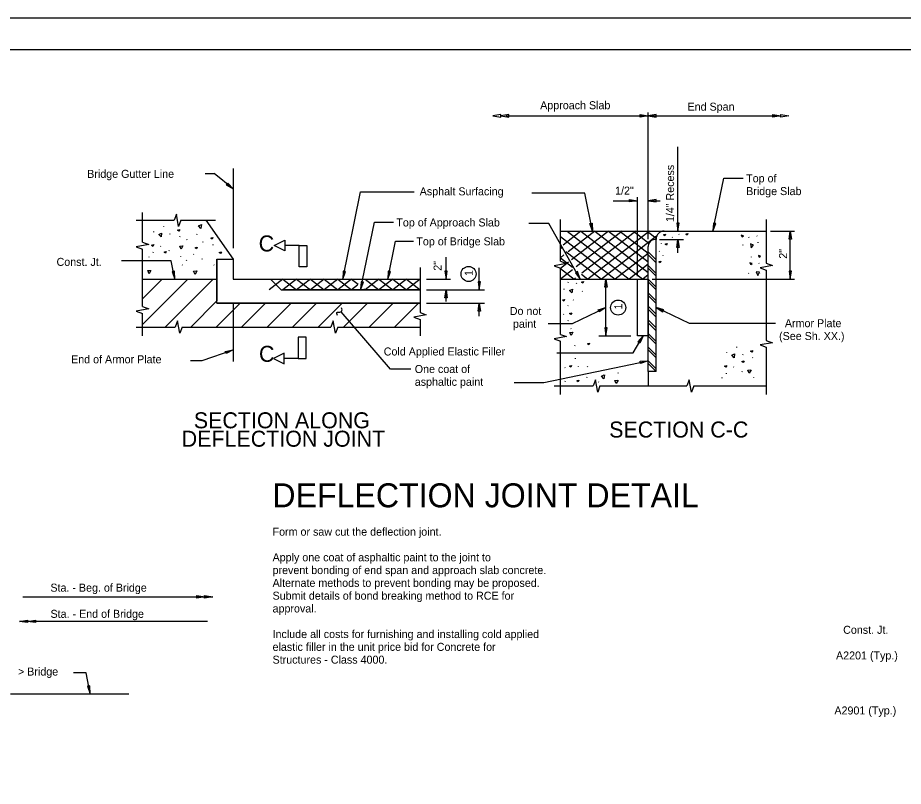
# Model space of a CAD drawing. Extents: x -129.8 to -33.5, y -497.5 to -438.8.
# Drawn here: x -89.34 to -52.46, y -470.81 to -438.78 of the extents above; entities that cross this region are included whole.
import ezdxf

# ---------------------------------------------------------------- set-up
doc = ezdxf.new("R2010")
doc.units = 0
for name, color, linetype in [('BR_AUTO DIMENSION', 7, 'Continuous'), ('BR_BORDER LINES', 7, 'Continuous'), ('BR_CENTER LINES', 7, 'Continuous'), ('BR_CONCRETE', 7, 'Continuous'), ('BR_STRUCTURAL STEEL', 7, 'Continuous'), ('BR_TABLE LINES', 7, 'Continuous'), ('BR_TEXT', 7, 'Continuous'), ('Default', 7, 'Continuous'), ('RD_SHT_IplotShp', 7, 'Continuous')]:
    doc.layers.add(name, color=color, linetype=linetype)

# ---------------------------------------------------------------- blocks, each defined once
blk = doc.blocks.new('CONCRT')
at = {"layer": 'Default'}
for p, q in [((-1.318, 1.18), (-1.295, 1.146)), ((0.991, 0.781), (1.013, 0.831)), ((1.319, 1.192), (1.341, 1.159)), ((-0.324, 0.653), (-0.302, 0.703)), ((0.37, 0.298), (0.392, 0.265)), ((-1.223, -0.529), (-1.201, -0.479)), ((-0.38, -0.757), (-0.357, -0.707)), ((0.125, -1.4), (0.148, -1.35)), ((0.94, -0.896), (0.946, -0.946))]:
    blk.add_line(p, q, dxfattribs=at)
for points in [[(-1.073, 0.503), (-0.924, 0.786), (-0.807, 0.526), (-1.068, 0.503)], [(0.952, 0.154), (1.019, 0.292), (1.13, 0.209), (0.952, 0.154)], [(-0.49, -0.243), (-0.423, -0.104), (-0.312, -0.188), (-0.49, -0.243)], [(0.296, -0.814), (0.34, -0.497), (0.538, -0.702), (0.301, -0.812)], [(-1.212, -1.112), (-1.146, -0.973), (-1.035, -1.056), (-1.212, -1.112)]]:
    blk.add_lwpolyline(points, dxfattribs=at)

msp = doc.modelspace()

# ---------------------------------------------------------------- linework, layer by layer
at = {"layer": 'BR_AUTO DIMENSION'}
for p, q in [((-69.004, -442.871), (-57.581, -442.871)), ((-63.084, -448.01), (-63.084, -442.729)), ((-61.841, -447.675), (-61.841, -444.157)), ((-80.362, -445.067), (-80.362, -448.386)), ((-81.535, -445.277), (-81.161, -445.277)), ((-80.362, -445.919), (-81.161, -445.277)), ((-60.382, -447.675), (-59.935, -445.476)), ((-59.935, -445.476), (-59.122, -445.476)), ((-75.801, -449.675), (-75.061, -446.035)), ((-75.061, -446.035), (-72.82, -446.035)), ((-65.715, -446.091), (-67.929, -446.091)), ((-65.394, -447.675), (-65.715, -446.091)), ((-64.544, -446.408), (-63.528, -446.408)), ((-63.528, -449.552), (-63.528, -446.265)), ((-63.084, -446.408), (-62.58, -446.408)), ((-84.397, -447.22), (-82.827, -447.22)), ((-82.538, -447.22), (-81.095, -447.22)), ((-75.056, -450.119), (-74.484, -447.304)), ((-74.484, -447.304), (-73.682, -447.304)), ((-67.211, -447.356), (-68.047, -447.356)), ((-65.907, -449.675), (-67.211, -447.356)), ((-58.164, -447.187), (-58.164, -449.014)), ((-57.99, -447.675), (-56.985, -447.675)), ((-57.163, -449.675), (-57.163, -447.675)), ((-73.923, -449.675), (-73.602, -448.091)), ((-73.602, -448.091), (-72.858, -448.091)), ((-62.607, -448.029), (-61.607, -448.029)), ((-61.841, -448.575), (-61.841, -448.029)), ((-71.5, -449.675), (-71.5, -448.764)), ((-82.941, -448.911), (-85.008, -448.911)), ((-82.798, -449.675), (-82.941, -448.911)), ((-72.578, -449.197), (-72.578, -451.072)), ((-70.113, -450.119), (-70.113, -449.209)), ((-58.164, -449.304), (-58.164, -452.229)), ((-72.306, -449.675), (-71.313, -449.675)), ((-64.84, -452.045), (-64.84, -449.675)), ((-62.914, -449.675), (-56.985, -449.675)), ((-72.306, -450.119), (-69.898, -450.119)), ((-71.5, -450.605), (-71.5, -450.119)), ((-72.306, -450.675), (-69.898, -450.675)), ((-70.113, -451.22), (-70.113, -450.675)), ((-73.813, -453.428), (-75.872, -451.04)), ((-66.229, -451.529), (-64.84, -450.86)), ((-61.361, -451.529), (-62.75, -450.86)), ((-72.578, -451.361), (-72.578, -452.045)), ((-84.397, -451.675), (-82.781, -451.675)), ((-82.492, -451.675), (-76.296, -451.675)), ((-76.007, -451.675), (-72.578, -451.675)), ((-67.241, -451.529), (-66.229, -451.529)), ((-57.78, -451.529), (-61.361, -451.529)), ((-65.132, -452.045), (-63.802, -452.045)), ((-63.711, -452.742), (-63.289, -452.042)), ((-58.164, -452.518), (-58.164, -454.491)), ((-81.653, -453.074), (-80.362, -452.623)), ((-66.888, -452.742), (-63.711, -452.742)), ((-82.141, -453.074), (-81.653, -453.074)), ((-67.428, -453.991), (-63.084, -453.076)), ((-72.962, -453.428), (-73.813, -453.428)), ((-68.662, -453.991), (-67.428, -453.991)), ((-66.993, -454.124), (-65.377, -454.124)), ((-65.088, -454.124), (-61.47, -454.124)), ((-61.181, -454.124), (-58.164, -454.124)), ((-89.124, -462.917), (-81.217, -462.917)), ((-81.436, -463.941), (-89.258, -463.941)), ((-86.483, -466.077), (-87.016, -466.077)), ((-86.317, -466.964), (-86.483, -466.077))]:
    msp.add_line(p, q, dxfattribs=at)
for points in [[(-69.218, -442.821), (-69.551, -442.871), (-69.218, -442.921)], [(-68.885, -442.821), (-69.218, -442.871), (-68.885, -442.921)], [(-63.417, -442.821), (-63.084, -442.871), (-63.417, -442.921)], [(-62.751, -442.821), (-63.084, -442.871), (-62.751, -442.921)], [(-57.883, -442.821), (-57.55, -442.871), (-57.883, -442.921)], [(-57.55, -442.821), (-57.217, -442.871), (-57.55, -442.921)], [(-80.653, -445.749), (-80.362, -445.919), (-80.59, -445.671)], [(-63.862, -446.358), (-63.528, -446.408), (-63.862, -446.458)], [(-62.751, -446.358), (-63.084, -446.408), (-62.751, -446.458)], [(-65.411, -447.338), (-65.394, -447.675), (-65.509, -447.358)], [(-61.891, -447.341), (-61.841, -447.675), (-61.791, -447.341)], [(-60.364, -447.338), (-60.382, -447.675), (-60.266, -447.358)], [(-57.213, -448.008), (-57.163, -447.675), (-57.113, -448.008)], [(-61.891, -448.363), (-61.841, -448.029), (-61.791, -448.363)], [(-82.909, -449.356), (-82.798, -449.675), (-82.81, -449.338)], [(-75.783, -449.338), (-75.801, -449.675), (-75.685, -449.358)], [(-73.906, -449.338), (-73.923, -449.675), (-73.808, -449.358)], [(-71.55, -449.341), (-71.5, -449.675), (-71.45, -449.341)], [(-66.114, -449.409), (-65.907, -449.675), (-66.027, -449.36)], [(-57.213, -449.341), (-57.163, -449.675), (-57.113, -449.341)], [(-75.039, -449.783), (-75.056, -450.119), (-74.941, -449.802)], [(-70.163, -449.786), (-70.113, -450.119), (-70.063, -449.786)], [(-64.89, -450.008), (-64.84, -449.675), (-64.79, -450.008)], [(-71.55, -450.452), (-71.5, -450.119), (-71.45, -450.452)], [(-70.163, -451.008), (-70.113, -450.675), (-70.063, -451.008)], [(-65.165, -450.951), (-64.84, -450.86), (-65.124, -451.042)], [(-62.425, -450.951), (-62.75, -450.86), (-62.466, -451.042)], [(-64.89, -451.712), (-64.84, -452.045), (-64.79, -451.712)], [(-63.511, -452.296), (-63.289, -452.042), (-63.427, -452.35)], [(-80.693, -452.686), (-80.362, -452.623), (-80.66, -452.78)], [(-63.42, -453.099), (-63.084, -453.076), (-63.399, -453.197)], [(-81.884, -462.867), (-81.55, -462.917), (-81.884, -462.967)], [(-81.551, -462.867), (-81.217, -462.917), (-81.551, -462.967)], [(-88.925, -463.991), (-89.258, -463.941), (-88.925, -463.891)], [(-88.592, -463.991), (-88.925, -463.941), (-88.592, -463.891)], [(-86.427, -466.645), (-86.317, -466.964), (-86.329, -466.627)]]:
    msp.add_lwpolyline(points, close=True, dxfattribs=at)
for points in [[(-84.14, -448.14), (-84.14, -446.897)], [(-82.538, -447.22), (-82.634, -447.477), (-82.73, -446.963), (-82.827, -447.22)], [(-66.736, -448.929), (-66.736, -447.187)], [(-84.14, -448.14), (-83.882, -448.236), (-84.397, -448.333), (-84.14, -448.429)], [(-84.14, -450.819), (-84.14, -448.429)], [(-66.736, -448.929), (-66.478, -449.025), (-66.993, -449.122), (-66.736, -449.218)], [(-58.164, -449.014), (-57.906, -449.111), (-58.421, -449.207), (-58.164, -449.304)], [(-66.736, -451.978), (-66.736, -449.218)], [(-84.14, -450.819), (-83.882, -450.915), (-84.397, -451.012), (-84.14, -451.108)], [(-84.14, -452.045), (-84.14, -451.108)], [(-72.578, -451.072), (-72.32, -451.168), (-72.835, -451.265), (-72.578, -451.361)], [(-82.492, -451.675), (-82.588, -451.932), (-82.685, -451.417), (-82.781, -451.675)], [(-76.007, -451.675), (-76.103, -451.932), (-76.2, -451.417), (-76.296, -451.675)], [(-66.736, -451.978), (-66.478, -452.074), (-66.993, -452.171), (-66.736, -452.267)], [(-66.736, -454.491), (-66.736, -452.267)], [(-58.164, -452.229), (-57.906, -452.325), (-58.421, -452.421), (-58.164, -452.518)], [(-65.088, -454.124), (-65.184, -454.382), (-65.281, -453.867), (-65.377, -454.124)], [(-61.181, -454.124), (-61.277, -454.382), (-61.374, -453.867), (-61.47, -454.124)]]:
    msp.add_lwpolyline(points, dxfattribs=at)
at = {"layer": 'BR_BORDER LINES'}
for p, q in [((-129.766, -438.782), (-33.766, -438.782)), ((-35.099, -440.119), (-124.877, -440.119))]:
    msp.add_line(p, q, dxfattribs=at)
at = {"layer": 'BR_CENTER LINES'}
for p, q in [((-82.253, -449.675), (-84.14, -451.561)), ((-83.314, -449.675), (-84.14, -450.5)), ((-81.193, -449.675), (-83.193, -451.675)), ((-81.038, -450.581), (-82.132, -451.675)), ((-80.071, -450.675), (-81.071, -451.675)), ((-79.011, -450.675), (-80.011, -451.675)), ((-77.95, -450.675), (-78.95, -451.675)), ((-76.889, -450.675), (-77.889, -451.675)), ((-75.829, -450.675), (-76.829, -451.675)), ((-74.768, -450.675), (-75.768, -451.675)), ((-73.707, -450.675), (-74.707, -451.675)), ((-72.647, -450.675), (-73.647, -451.675)), ((-89.634, -466.964), (-84.715, -466.964))]:
    msp.add_line(p, q, dxfattribs=at)
at = {"layer": 'BR_CONCRETE'}
for p, q in [((-62.417, -447.675), (-58.164, -447.675)), ((-62.751, -448.008), (-62.751, -448.029)), ((-81.038, -448.851), (-80.362, -448.851)), ((-84.14, -449.675), (-81.038, -449.675)), ((-80.362, -449.675), (-72.578, -449.675)), ((-66.736, -449.675), (-63.528, -449.675)), ((-81.038, -450.675), (-72.578, -450.675)), ((-63.084, -453.527), (-63.084, -454.124))]:
    msp.add_line(p, q, dxfattribs=at)
msp.add_lwpolyline([(-81.503, -447.22), (-80.362, -448.851), (-80.362, -449.675)], dxfattribs=at)
msp.add_arc((-62.417, -448.008), 0.333, 90, 180, dxfattribs=at)
at = {"layer": 'BR_STRUCTURAL STEEL'}
for p, q in [((-62.751, -448.029), (-62.8, -448.029)), ((-62.751, -453.527), (-62.751, -448.029)), ((-63.084, -453.527), (-63.084, -448.314)), ((-63.084, -448.541), (-62.751, -448.874)), ((-63.084, -448.659), (-62.751, -448.992)), ((-63.084, -449.108), (-62.751, -449.441)), ((-63.084, -449.226), (-62.751, -449.559)), ((-63.084, -449.675), (-62.751, -450.008)), ((-63.084, -449.793), (-62.751, -450.126)), ((-63.084, -450.242), (-62.751, -450.575)), ((-63.084, -450.359), (-62.751, -450.693)), ((-63.084, -450.808), (-62.751, -451.142)), ((-63.084, -450.926), (-62.751, -451.26)), ((-63.084, -451.375), (-62.751, -451.709)), ((-63.084, -451.493), (-62.751, -451.826)), ((-63.084, -451.942), (-62.751, -452.275)), ((-63.084, -452.06), (-62.751, -452.393)), ((-63.084, -452.509), (-62.751, -452.842)), ((-63.084, -452.627), (-62.751, -452.96)), ((-63.084, -453.076), (-62.751, -453.409)), ((-63.084, -453.194), (-62.751, -453.527)), ((-62.751, -453.527), (-63.084, -453.527))]:
    msp.add_line(p, q, dxfattribs=at)
msp.add_arc((-62.8, -448.314), 0.284, 90, 180, dxfattribs=at)
at = {"layer": 'BR_TABLE LINES'}
for p, q in [((-83.666, -447.715), (-83.669, -447.69)), ((-83.259, -447.463), (-83.27, -447.488)), ((-66.736, -447.675), (-62.417, -447.675)), ((-65.879, -447.675), (-66.626, -448.256)), ((-66.45, -447.675), (-63.879, -449.675)), ((-65.307, -447.675), (-66.417, -448.538)), ((-64.736, -447.675), (-66.267, -448.866)), ((-64.164, -447.675), (-66.074, -449.16)), ((-65.879, -447.675), (-63.307, -449.675)), ((-63.593, -447.675), (-65.841, -449.423)), ((-63.021, -447.675), (-65.593, -449.675)), ((-65.307, -447.675), (-63.084, -449.404)), ((-64.736, -447.675), (-63.084, -448.959)), ((-64.265, -447.675), (-63.084, -448.594)), ((-63.694, -447.675), (-63.049, -448.177)), ((-63.123, -447.675), (-62.748, -447.966)), ((-83.006, -447.785), (-83.017, -447.81)), ((-82.585, -447.899), (-82.596, -447.924)), ((-82.286, -448.055), (-82.289, -448.03)), ((-81.879, -447.802), (-81.89, -447.827)), ((-66.736, -447.897), (-64.45, -449.675)), ((-62.73, -447.893), (-65.021, -449.675)), ((-62.074, -447.939), (-62.085, -447.922)), ((-61.793, -447.817), (-61.804, -447.801)), ((-58.904, -447.915), (-58.893, -447.94)), ((-58.556, -447.867), (-58.545, -447.892)), ((-83.381, -448.312), (-83.392, -448.296)), ((-81.626, -448.124), (-81.638, -448.149)), ((-81.205, -448.238), (-81.216, -448.263)), ((-77.619, -448.276), (-78.211, -448.276)), ((-66.736, -448.341), (-66.676, -448.388)), ((-62.52, -448.192), (-62.531, -448.176)), ((-59.156, -448.237), (-59.145, -448.262)), ((-58.496, -448.167), (-58.494, -448.142)), ((-83.856, -448.759), (-83.867, -448.743)), ((-83.692, -448.554), (-83.703, -448.579)), ((-83.034, -448.49), (-83.045, -448.515)), ((-82.537, -448.753), (-82.548, -448.736)), ((-82.001, -448.651), (-82.012, -448.635)), ((-81.654, -448.829), (-81.665, -448.854)), ((-66.587, -448.67), (-66.736, -448.786)), ((-66.736, -448.786), (-66.238, -449.173)), ((-66.508, -448.519), (-65.021, -449.675)), ((-63.084, -448.612), (-64.45, -449.675)), ((-62.613, -448.527), (-62.624, -448.51)), ((-62.45, -448.706), (-62.461, -448.689)), ((-58.782, -448.764), (-58.771, -448.747)), ((-82.476, -449.099), (-82.487, -449.082)), ((-82.312, -448.893), (-82.323, -448.918)), ((-81.157, -449.092), (-81.169, -449.076)), ((-66.394, -448.964), (-66.736, -449.23)), ((-63.084, -449.057), (-63.879, -449.675)), ((-58.471, -449.005), (-58.46, -449.03)), ((-66.736, -449.23), (-66.164, -449.675)), ((-66.233, -449.284), (-66.736, -449.675)), ((-65.854, -449.472), (-65.593, -449.675)), ((-63.084, -449.501), (-63.307, -449.675)), ((-58.905, -449.446), (-58.893, -449.429)), ((-58.453, -449.404), (-58.442, -449.429)), ((-78.292, -449.675), (-78.863, -450.119)), ((-78.292, -449.675), (-77.721, -450.119)), ((-77.721, -449.675), (-78.292, -450.119)), ((-77.149, -449.675), (-77.721, -450.119)), ((-77.721, -449.675), (-77.149, -450.119)), ((-77.149, -449.675), (-76.578, -450.119)), ((-76.578, -449.675), (-77.149, -450.119)), ((-76.006, -449.675), (-76.578, -450.119)), ((-76.578, -449.675), (-76.006, -450.119)), ((-76.006, -449.675), (-75.435, -450.119)), ((-75.435, -449.675), (-76.006, -450.119)), ((-75.435, -449.675), (-75.165, -449.885)), ((-75.187, -449.927), (-75.435, -450.119)), ((-74.863, -449.675), (-74.292, -450.119)), ((-74.292, -449.675), (-74.863, -450.119)), ((-74.863, -449.675), (-74.863, -449.675)), ((-73.721, -449.675), (-74.292, -450.119)), ((-74.292, -449.675), (-73.721, -450.119)), ((-73.721, -449.675), (-73.149, -450.119)), ((-73.149, -449.675), (-73.721, -450.119)), ((-72.578, -449.675), (-73.149, -450.119)), ((-73.149, -449.675), (-72.578, -450.119)), ((-66.419, -449.802), (-66.43, -449.827)), ((-66.104, -449.628), (-66.164, -449.675)), ((-66.071, -449.85), (-66.082, -449.875)), ((-74.916, -450.079), (-74.863, -450.119)), ((-66.573, -450.102), (-66.576, -450.077)), ((-65.819, -450.172), (-65.83, -450.197)), ((-66.193, -450.556), (-66.204, -450.54)), ((-66.413, -450.77), (-66.424, -450.795)), ((-66.6, -451.146), (-66.611, -451.13)), ((-66.413, -451.406), (-66.424, -451.431)), ((-66.289, -451.748), (-66.3, -451.731)), ((-66.131, -452.443), (-66.142, -452.467)), ((-77.652, -452.978), (-78.245, -452.978)), ((-66.111, -452.994), (-66.114, -452.969)), ((-66.54, -453.377), (-66.551, -453.36)), ((-65.978, -453.316), (-65.989, -453.299)), ((-65.608, -453.317), (-65.619, -453.342)), ((-64.337, -453.585), (-64.348, -453.61)), ((-66.538, -453.928), (-66.55, -453.953)), ((-65.636, -453.766), (-65.647, -453.791)), ((-65.139, -453.976), (-65.15, -453.959))]:
    msp.add_line(p, q, dxfattribs=at)
for points in [[(-82.59, -447.607), (-82.623, -447.677), (-82.679, -447.635), (-82.59, -447.607)], [(-81.684, -447.405), (-81.706, -447.564), (-81.805, -447.461), (-81.686, -447.406)], [(-83.344, -447.756), (-83.366, -447.915), (-83.465, -447.812), (-83.347, -447.757)], [(-81.21, -447.947), (-81.244, -448.016), (-81.299, -447.974), (-81.21, -447.947)], [(-62.36, -447.805), (-62.393, -447.874), (-62.448, -447.833), (-62.36, -447.805)], [(-61.428, -447.773), (-61.461, -447.842), (-61.517, -447.801), (-61.428, -447.773)], [(-59.206, -447.846), (-59.172, -447.915), (-59.117, -447.873), (-59.206, -447.846)], [(-83.672, -448.24), (-83.706, -448.31), (-83.761, -448.268), (-83.672, -448.24)], [(-82.454, -448.287), (-82.529, -448.429), (-82.588, -448.298), (-82.457, -448.287)], [(-81.863, -448.345), (-81.896, -448.414), (-81.952, -448.372), (-81.863, -448.345)], [(-62.287, -448.19), (-62.32, -448.259), (-62.375, -448.218), (-62.287, -448.19)], [(-58.819, -448.208), (-58.797, -448.367), (-58.697, -448.264), (-58.816, -448.209)], [(-83.149, -448.521), (-83.183, -448.591), (-83.238, -448.549), (-83.149, -448.521)], [(-80.854, -448.535), (-80.887, -448.605), (-80.943, -448.563), (-80.854, -448.535)], [(-58.49, -448.692), (-58.457, -448.761), (-58.401, -448.72), (-58.49, -448.692)], [(-62.548, -448.928), (-62.581, -448.997), (-62.637, -448.956), (-62.548, -448.928)], [(-58.843, -449.003), (-58.809, -449.072), (-58.754, -449.031), (-58.843, -449.003)], [(-83.786, -449.311), (-83.861, -449.452), (-83.919, -449.322), (-83.789, -449.311)], [(-81.878, -449.337), (-81.953, -449.479), (-82.011, -449.348), (-81.881, -449.337)], [(-58.585, -449.378), (-58.51, -449.52), (-58.451, -449.389), (-58.582, -449.378)], [(-65.769, -449.781), (-65.803, -449.85), (-65.858, -449.809), (-65.769, -449.781)], [(-66.232, -450.088), (-66.254, -450.247), (-66.354, -450.144), (-66.235, -450.089)], [(-66.566, -450.519), (-66.6, -450.588), (-66.655, -450.546), (-66.566, -450.519)], [(-66.265, -451.079), (-66.299, -451.148), (-66.354, -451.107), (-66.265, -451.079)], [(-66.212, -451.885), (-66.287, -452.026), (-66.345, -451.896), (-66.215, -451.885)], [(-65.52, -452.339), (-65.553, -452.409), (-65.608, -452.367), (-65.52, -452.339)], [(-66.274, -453.278), (-66.307, -453.348), (-66.363, -453.306), (-66.274, -453.278)], [(-65.967, -453.888), (-66.001, -453.957), (-66.056, -453.916), (-65.967, -453.888)], [(-64.904, -453.669), (-64.926, -453.828), (-65.025, -453.725), (-64.907, -453.67)], [(-64.337, -453.883), (-64.412, -454.024), (-64.47, -453.894), (-64.34, -453.883)]]:
    msp.add_lwpolyline(points, dxfattribs=at)
for points in [[(-78.211, -448.498), (-78.656, -448.276), (-78.211, -448.053)], [(-77.293, -449.165), (-77.619, -449.165), (-77.619, -448.276), (-77.293, -448.276)], [(-81.038, -448.851), (-80.362, -448.851), (-80.362, -449.675), (-78.806, -449.675), (-78.362, -450.119), (-72.578, -450.119), (-72.578, -450.675), (-81.038, -450.675)], [(-63.528, -449.675), (-63.084, -449.675), (-63.084, -452.045), (-63.528, -452.045)], [(-77.326, -452.089), (-77.652, -452.089), (-77.652, -452.978), (-77.326, -452.978)], [(-78.245, -452.756), (-78.689, -452.978), (-78.245, -453.2)]]:
    msp.add_lwpolyline(points, close=True, dxfattribs=at)
msp.add_spline([(-76.016, -451.186), (-76.044, -451.064), (-75.876, -451.042), (-75.847, -451.019), (-75.83, -450.953), (-75.858, -450.879)], degree=3, dxfattribs=at)
at = {"layer": 'BR_TEXT'}
for p, q in [((-81.038, -448.851), (-81.038, -450.581)), ((-78.362, -450.119), (-78.806, -449.675)), ((-78.362, -450.119), (-72.578, -450.119)), ((-72.578, -450.119), (-78.292, -450.119)), ((-80.362, -450.675), (-80.362, -453.109))]:
    msp.add_line(p, q, dxfattribs=at)
for centre in [(-70.561, -449.462), (-64.332, -450.863)]:
    msp.add_circle(centre, 0.314, dxfattribs=at)
at = {"layer": 'RD_SHT_IplotShp'}
msp.add_lwpolyline([(-129.766, -438.786), (-33.766, -438.786), (-33.766, -497.453), (-129.766, -497.453)], close=True, dxfattribs=at)

# ---------------------------------------------------------------- block references
at = {"layer": 'BR_TABLE LINES', "xscale": 0.5, "yscale": 0.5, "rotation": 180}
msp.add_blockref('CONCRT', (-59.333, -453.201), dxfattribs=at)

# ---------------------------------------------------------------- texts
at = {"layer": 'BR_TEXT'}
for s, height, p in [('Approach Slab', 0.3333, (-67.578, -442.596)), ('End Span', 0.3333, (-61.441, -442.656)), ('Top of ', 0.3333, (-59, -445.642)), ('Asphalt Surfacing', 0.3333, (-72.595, -446.185)), ('1/2"', 0.3333, (-64.459, -446.156)), ('Bridge Slab', 0.3333, (-59, -446.175)), ('Top of Approach Slab', 0.3333, (-73.569, -447.482)), ('Top of Bridge Slab', 0.3333, (-72.735, -448.269)), ('Do not', 0.3333, (-68.844, -451.171)), ('paint', 0.3333, (-68.711, -451.705)), ('Cold Applied Elastic Filler', 0.3333, (-74.093, -452.859)), ('One coat of', 0.3333, (-72.801, -453.589)), ('asphaltic paint', 0.3333, (-72.801, -454.122)), ('SECTION ALONG', 0.6668, (-82.002, -455.893)), ('SECTION C-C', 0.6668, (-64.705, -456.277)), ('DEFLECTION JOINT', 0.6668, (-82.506, -456.66)), ('DEFLECTION JOINT DETAIL', 1.0001, (-78.732, -459.186)), ('Const. Jt.', 0.3333, (-54.96, -464.457)), ('A2201 (Typ.)', 0.3333, (-55.258, -465.526)), ('A2901 (Typ.)', 0.3333, (-55.325, -467.818))]:
    msp.add_text(s, height=height, dxfattribs=at).set_placement(p)
for s, height, rotation, p in [('Bridge Gutter Line', 0.3333, 360, (-86.442, -445.456)), ('1/4" Recess', 0.33333, 90, (-62.002, -447.301)), ('C', 0.667, 360, (-79.302, -448.523)), ('2"', 0.3333, 90, (-57.296, -448.826)), ('Const. Jt.', 0.3333, 360, (-87.719, -449.125)), ('2"', 0.3333, 90, (-71.684, -449.327)), ('1', 0.333, 90, (-70.385, -449.544)), ('1', 0.333, 90, (-64.158, -450.941)), ('Armor Plate', 0.3333, 360, (-57.387, -451.679)), ('(See Sh. XX.)', 0.3333, 360, (-57.629, -452.213)), ('C', 0.667, 360, (-79.288, -453.123)), ('End of Armor Plate', 0.3333, 360, (-87.114, -453.184)), ('Form or saw cut the deflection joint.', 0.3333, 360, (-78.723, -460.368)), ('Apply one coat of asphaltic paint to the joint to', 0.3333, 360, (-78.723, -461.435)), ('prevent bonding of end span and approach slab concrete.', 0.3333, 360, (-78.723, -461.968)), ('Sta. - Beg. of Bridge', 0.3333, 360, (-87.976, -462.7)), ('Alternate methods to prevent bonding may be proposed.', 0.3333, 360, (-78.723, -462.501)), ('Submit details of bond breaking method to RCE for', 0.3333, 360, (-78.723, -463.035)), ('approval.', 0.3333, 360, (-78.723, -463.568)), ('Sta. - End of Bridge', 0.3333, 360, (-87.97, -463.791)), ('Include all costs for furnishing and installing cold applied', 0.3333, 360, (-78.723, -464.634)), ('elastic filler in the unit price bid for Concrete for', 0.3333, 360, (-78.723, -465.168)), ('Structures - Class 4000.', 0.3333, 360, (-78.723, -465.701)), ('> Bridge', 0.3333, 360, (-89.324, -466.197))]:
    msp.add_text(s, height=height, rotation=rotation, dxfattribs=at).set_placement(p)

doc.saveas('drawing.dxf')
